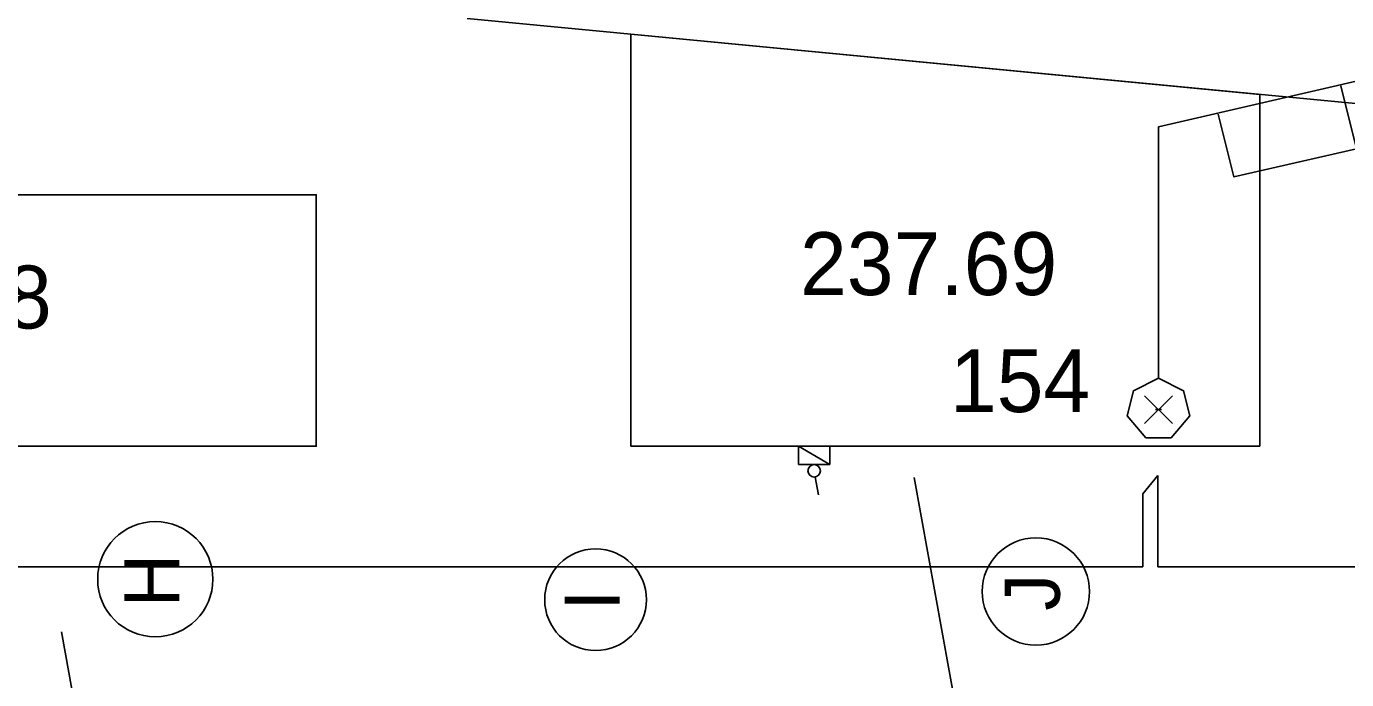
# Model space of a CAD drawing. Extents: x -264222 to -263592, y -1242345 to -1242048.
# Drawn here: x -263871.58 to -263850.59, y -1242082.09 to -1242071.7 of the extents above; entities that cross this region are included whole.
import ezdxf

# ---------------------------------------------------------------- set-up
doc = ezdxf.new("R2010")
doc.units = 0
for name, color, linetype in [('BOD_CISLO', 7, 'Continuous'), ('BOD_SYMBOL', 7, 'Continuous'), ('BOD_VYSKA', 7, 'Continuous'), ('HESCON_OSI_STAVBY_KFA', 7, 'Continuous'), ('KFA_2D_SITUACIA_DSP', 7, 'Continuous'), ('KFA_SO_62-1_VO_LAMPY_MERANE', 7, 'Continuous'), ('KFA_SO_62-1_VO_TRASA_KABLOV_PROJEKT', 7, 'Continuous')]:
    doc.layers.add(name, color=color, linetype=linetype)

msp = doc.modelspace()

# ---------------------------------------------------------------- linework, layer by layer
at = {"layer": 'BOD_SYMBOL'}
for p, q in [((-263853.799, -1242078.02), (-263853.357, -1242077.578)), ((-263853.357, -1242078.02), (-263853.799, -1242077.578))]:
    msp.add_line(p, q, dxfattribs=at)
at = {"layer": 'HESCON_OSI_STAVBY_KFA'}
for centre, radius in [((-263869.528, -1242080.498), 0.916), ((-263855.528, -1242080.693), 0.853), ((-263862.528, -1242080.824), 0.809)]:
    msp.add_circle(centre, radius, dxfattribs=at)
at = {"layer": 'KFA_2D_SITUACIA_DSP'}
for p, q in [((-263765.366, -1242081.09), (-263864.57, -1242071.577)), ((-263861.968, -1242078.382), (-263861.968, -1242071.826)), ((-263861.968, -1242071.826), (-263851.968, -1242072.785)), ((-263851.968, -1242072.785), (-263851.968, -1242078.382)), ((-263851.968, -1242078.382), (-263861.968, -1242078.382)), ((-263859.303, -1242078.673), (-263859.303, -1242078.383)), ((-263859.303, -1242078.383), (-263858.803, -1242078.383)), ((-263858.803, -1242078.673), (-263859.303, -1242078.383)), ((-263858.803, -1242078.673), (-263859.303, -1242078.383)), ((-263859.303, -1242078.383), (-263859.303, -1242078.673)), ((-263858.803, -1242078.383), (-263858.803, -1242078.673)), ((-263858.803, -1242078.673), (-263859.303, -1242078.673)), ((-263859.303, -1242078.673), (-263858.803, -1242078.673)), ((-263859.035, -1242078.872), (-263858.983, -1242079.157)), ((-263855.881, -1242087.633), (-263857.462, -1242078.882)), ((-263869.881, -1242087.633), (-263871.02, -1242081.332))]:
    msp.add_line(p, q, dxfattribs=at)
msp.add_lwpolyline([(-263881.968, -1242074.382), (-263866.968, -1242074.382), (-263866.968, -1242078.382), (-263881.968, -1242078.382)], close=True, dxfattribs=at)
msp.add_circle((-263859.053, -1242078.773), 0.1, dxfattribs=at)
at = {"layer": 'KFA_SO_62-1_VO_LAMPY_MERANE'}
for p, q in [((-263853.628, -1242077.799), (-263853.528, -1242077.799)), ((-263853.578, -1242077.799), (-263853.578, -1242077.799))]:
    msp.add_line(p, q, dxfattribs=at)
for points in [[(-263853.578, -1242077.299), (-263853.978, -1242077.499), (-263854.078, -1242077.899), (-263853.778, -1242078.249), (-263853.378, -1242078.249), (-263853.078, -1242077.899), (-263853.178, -1242077.499), (-263853.578, -1242077.299), (-263853.578, -1242073.299), (-263849.678, -1242072.399)], [(-263850.678, -1242072.649), (-263850.428, -1242073.649), (-263852.378, -1242074.099), (-263852.628, -1242073.099)]]:
    msp.add_lwpolyline(points, dxfattribs=at)
at = {"layer": 'KFA_SO_62-1_VO_TRASA_KABLOV_PROJEKT'}
for p, q in [((-263853.59, -1242078.85), (-263853.825, -1242079.139)), ((-263853.59, -1242080.303), (-263853.59, -1242078.85)), ((-263853.825, -1242079.139), (-263853.825, -1242080.303)), ((-263853.825, -1242080.303), (-263876.07, -1242080.303)), ((-263837.33, -1242080.303), (-263853.59, -1242080.303))]:
    msp.add_line(p, q, dxfattribs=at)

# ---------------------------------------------------------------- texts
at = {"layer": 'BOD_CISLO'}
msp.add_text('154', height=1, dxfattribs=at).set_placement((-263856.895, -1242077.839))
at = {"layer": 'BOD_VYSKA'}
for s, p in [('237.69', (-263859.278, -1242075.978)), ('237.58', (-263875.265, -1242076.509))]:
    msp.add_text(s, height=1, dxfattribs=at).set_placement(p)
at = {"layer": 'HESCON_OSI_STAVBY_KFA'}
for s, p in [('H', (-263869.147, -1242080.939)), ('J', (-263855.147, -1242080.999)), ('I', (-263862.147, -1242080.994))]:
    msp.add_text(s, height=0.875, rotation=90, dxfattribs=at).set_placement(p)

doc.saveas('drawing.dxf')
